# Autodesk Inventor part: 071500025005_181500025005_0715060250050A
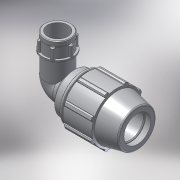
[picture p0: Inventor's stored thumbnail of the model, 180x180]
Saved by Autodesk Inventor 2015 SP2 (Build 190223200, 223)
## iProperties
Created: 2017-02
Part Number: 071500025005_181500025005_0715060250050A
Material: PVC-Piping
Description: PLASSON 90° ELBOW FEMALE ADAPTOR 25-1/2"
Document SubType Name: Modeling
Designer: KIM
Mass: 92.6774 g
Surface Area: 199.44 cm^2
Volume: 66.1981 cm^3
Density: 1.4 g/cm^3
Appearance: Smooth - White
Author: KIM
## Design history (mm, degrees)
derived "07150.ipt"
feature "Solid1::07150.ipt"
tag "TaggingFeature1"
body "Solid1"
other parameters: "d2" = 25, "d4" = 6.75, "d5" = 20.25, "d7" = 54, "d9" = 11.57143, "d11" = 2.7, "d13" = 120 deg, "d14" = 37.5, "d15" = 12 deg, "d16" = 46.98, "d18" = 1.25, "d19" = 35 deg, "d20" = 17.5 deg, "d21" = 50.22, "d23" = 0, "d25" = 360 deg, "d27" = 1.08, "d33" = 0.5, "d42" = 29.97, "d43" = 1.62, "d46" = 0.75, "d51" = 81, "d68" = 2.7, "d72" = 46, "d73" = 24.2203, "d74" = 18, "d75" = 27.85335, "d76" = 18.631, "d77" = 19.8, "d79" = 7.4524, "d80" = 0.55893, "d83" = 0, "d84" = 0, "d91" = 40.5, "d93" = 58, "d94" = 18.631, "d95" = 13.0417, "d96" = 8.1, "d97" = 50 deg, "d98" = 16.7679, "d99" = 0.5, "d100" = 0.5, "d101" = 6, "d102" = 24.2203, "d103" = 15.3, "d104" = 0, "d108" = 360 deg, "d110" = 0.72661, "d_" = 25, "E_" = 54, "A_" = 81, "l_" = 58, "l_2" = 18, "A_1" = 46, "Rp_" = 18.631, "d105" = 3.63304
